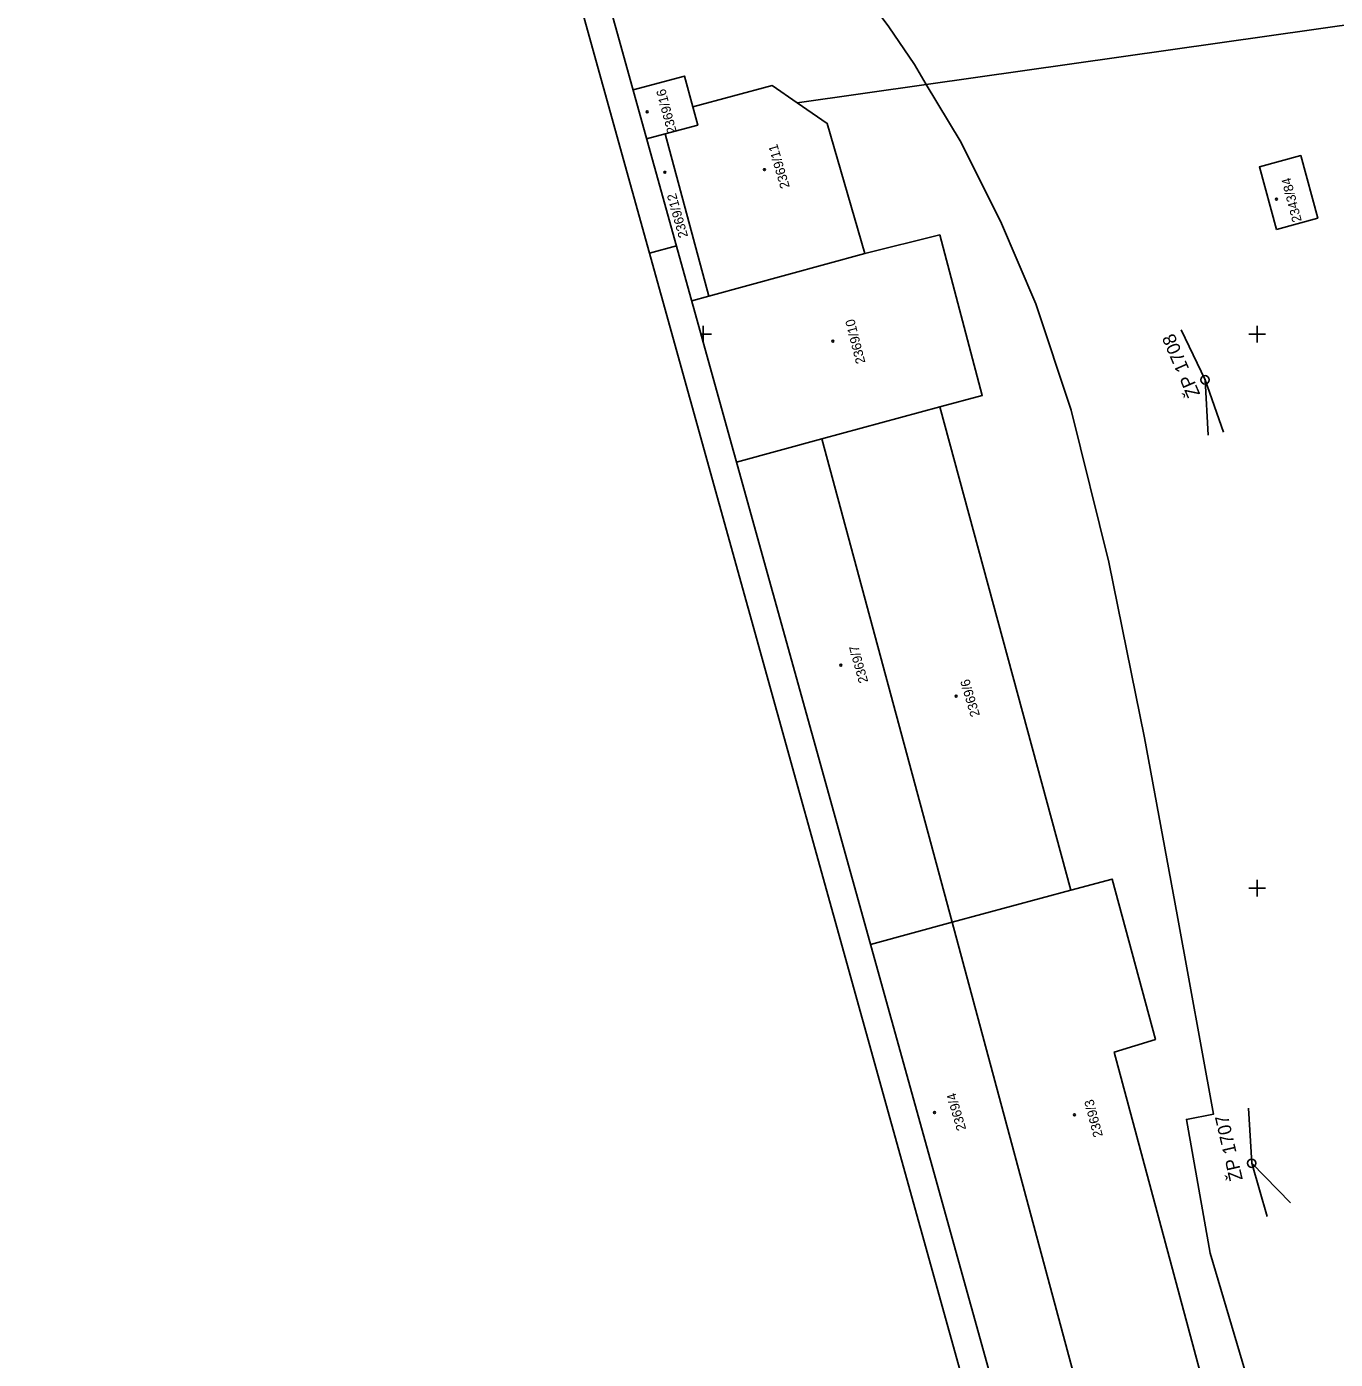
# Model space of a CAD drawing. Extents: x -821122 to -820555, y -1070892 to -1069801.
# Drawn here: x -821122.1 to -820885.9, y -1070485 to -1070244.5 of the extents above; entities that cross this region are included whole.
import ezdxf

# ---------------------------------------------------------------- set-up
doc = ezdxf.new("R2010")
doc.units = 0
for name, color, linetype in [('Hranice drážního pozemku', 7, 'Continuous'), ('Hranice parcel', 7, 'Continuous'), ('Parcelní čísla', 7, 'Continuous'), ('Ram', 7, 'Continuous'), ('Vrstva 61', 7, 'Continuous'), ('ZBP', 7, 'Continuous'), ('Značky budov', 7, 'Continuous')]:
    doc.layers.add(name, color=color, linetype=linetype)

msp = doc.modelspace()

# ---------------------------------------------------------------- linework, layer by layer
at = {"layer": 'Hranice drážního pozemku'}
for points in [[(-820959.73, -1070254.91), (-820961.88, -1070251.33), (-820966.49, -1070244.53), (-820975.99, -1070231.76), (-820986.52, -1070219.72), (-820997.71, -1070208.62), (-821016.02, -1070193.21), (-821033.38, -1070181.32)], [(-820768.36, -1070867.01), (-820772.76, -1070853.45), (-820780.56, -1070834.55), (-820786.59, -1070821.38), (-820797.89, -1070798.01), (-820802.49, -1070786.9), (-820807.86, -1070771.6), (-820839.34, -1070671.73), (-820847.49, -1070649.05), (-820862.12, -1070611.55), (-820870.18, -1070588.9), (-820893.88, -1070513.71), (-820901.78, -1070488.65), (-820908.48, -1070465.88), (-820912.77, -1070441.75), (-820907.91, -1070440.8), (-820914.43, -1070404.83), (-820920.34, -1070372.85), (-820926.76, -1070341.17), (-820933.59, -1070313.73), (-820939.94, -1070294.5), (-820946.33, -1070279.59), (-820953.63, -1070265.09), (-820959.73, -1070254.91)]]:
    msp.add_lwpolyline(points, dxfattribs=at)
at = {"layer": 'Hranice parcel'}
for p, q in [((-820959.73, -1070254.91), (-820835.88, -1070237.32)), ((-820959.73, -1070254.91), (-820983.06, -1070258.22)), ((-821006.88, -1070263.86), (-821010.2, -1070264.76)), ((-821006.88, -1070263.86), (-820998.99, -1070293.15)), ((-820970.82, -1070285.44), (-820998.99, -1070293.15)), ((-820998.99, -1070293.15), (-821002.07, -1070293.99)), ((-820957.29, -1070313.09), (-820978.59, -1070318.91)), ((-820957.29, -1070313.09), (-820933.62, -1070400.37)), ((-820978.59, -1070318.91), (-820993.99, -1070323.08)), ((-820978.59, -1070318.91), (-820955.07, -1070406.16)), ((-820933.62, -1070400.37), (-820955.07, -1070406.16)), ((-820955.07, -1070406.16), (-820969.8, -1070410.14)), ((-820955.07, -1070406.16), (-820931.21, -1070494.68))]:
    msp.add_line(p, q, dxfattribs=at)
for points in [[(-821033.38, -1070181.32), (-821016.02, -1070193.21), (-820997.71, -1070208.62), (-820986.52, -1070219.72), (-820975.99, -1070231.76), (-820966.49, -1070244.53), (-820961.88, -1070251.33), (-820959.73, -1070254.91)], [(-821001.88, -1070258.94), (-821003.37, -1070253.41), (-821012.65, -1070255.91)], [(-820983.06, -1070258.22), (-820987.52, -1070255.14), (-821001.88, -1070258.94)], [(-820768.36, -1070867.01), (-820772.76, -1070853.45), (-820780.56, -1070834.55), (-820786.59, -1070821.38), (-820797.89, -1070798.01), (-820802.49, -1070786.9), (-820807.86, -1070771.6), (-820839.34, -1070671.73), (-820847.49, -1070649.05), (-820862.12, -1070611.55), (-820870.18, -1070588.9), (-820893.88, -1070513.71), (-820901.78, -1070488.65), (-820908.48, -1070465.88), (-820912.77, -1070441.75), (-820907.91, -1070440.8), (-820914.43, -1070404.83), (-820920.34, -1070372.85), (-820926.76, -1070341.17), (-820933.59, -1070313.73), (-820939.94, -1070294.5), (-820946.33, -1070279.59), (-820953.63, -1070265.09), (-820959.73, -1070254.91)], [(-820983.06, -1070258.22), (-820977.6, -1070261.97), (-820970.82, -1070285.44)], [(-821001.88, -1070258.94), (-821000.98, -1070262.27), (-821006.88, -1070263.86)], [(-820896.54, -1070281.12), (-820899.6, -1070269.81), (-820892.15, -1070267.75), (-820889.06, -1070279.08), (-820896.54, -1070281.12)], [(-820970.82, -1070285.44), (-820957.3, -1070282.09), (-820949.63, -1070311.06), (-820957.29, -1070313.09)], [(-820933.62, -1070400.37), (-820926.16, -1070398.36), (-820918.36, -1070427.34), (-820925.8, -1070429.59), (-820909.9, -1070488.92), (-820931.21, -1070494.68)]]:
    msp.add_lwpolyline(points, dxfattribs=at)
at = {"layer": 'Ram'}
for p, q in [((-821004.84, -1070284.04), (-821009.66, -1070285.38)), ((-821009.66, -1070285.38), (-821004.84, -1070284.04))]:
    msp.add_line(p, q, dxfattribs=at)
for points in [[(-820837.51, -1070886.22), (-821115.94, -1069884.19), (-820839.42, -1069807.35)], [(-820840.99, -1070892.38), (-821122.1, -1069880.71)]]:
    msp.add_lwpolyline(points, dxfattribs=at)
at = {"layer": 'Vrstva 61'}
for p, q in [((-821000, -1070298.5), (-821000, -1070301.45)), ((-820900, -1070298.5), (-820900, -1070301.5)), ((-821000.4, -1070300), (-820998.5, -1070300)), ((-820901.5, -1070300), (-820898.5, -1070300)), ((-820901.5, -1070400), (-820898.5, -1070400)), ((-820900, -1070398.5), (-820900, -1070401.5))]:
    msp.add_line(p, q, dxfattribs=at)
at = {"layer": 'ZBP'}
for p, q in [((-820909.42, -1070308.24), (-820913.7, -1070299.2)), ((-820909.41, -1070308.28), (-820909.43, -1070308.19)), ((-820909.42, -1070308.24), (-820908.83, -1070318.22)), ((-820909.42, -1070308.24), (-820906.1, -1070317.67)), ((-820901, -1070449.66), (-820901.59, -1070439.68)), ((-820900.98, -1070449.71), (-820901.01, -1070449.61)), ((-820901, -1070449.66), (-820898.19, -1070459.26)), ((-820901, -1070449.66), (-820893.97, -1070456.77))]:
    msp.add_line(p, q, dxfattribs=at)
for centre in [(-820909.42, -1070308.24), (-820901, -1070449.66)]:
    msp.add_circle(centre, 0.756, dxfattribs=at)
at = {"layer": 'Značky budov'}
for centre in [(-821010.11, -1070259.85), (-820988.95, -1070270.3), (-821006.9, -1070270.78), (-820896.53, -1070275.64), (-820976.59, -1070301.24), (-820975.15, -1070359.75), (-820954.34, -1070365.35), (-820958.24, -1070440.5), (-820932.99, -1070440.92)]:
    msp.add_circle(centre, 0.175, dxfattribs=at)

# ---------------------------------------------------------------- texts
at = {"layer": 'Parcelní čísla'}
for s, rotation, p in [('2369/16', 104.9208, (-821004.74, -1070263.53)), ('2369/11', 106.2487, (-820984.35, -1070273.43)), ('2343/84', 104.6003, (-820891.94, -1070279.56)), ('2369/12', 105.7231, (-821002.71, -1070282.34)), ('2369/10', 104.2543, (-820970.71, -1070305.11)), ('2369/7', 105.4112, (-820970.2, -1070362.73)), ('2369/6', 106.4652, (-820950.03, -1070368.79)), ('2369/4', 106.2734, (-820952.51, -1070443.5)), ('2369/3', 104.6573, (-820927.84, -1070444.72))]:
    msp.add_text(s, height=1.7, rotation=rotation, dxfattribs=at).set_placement(p)
at = {"layer": 'ZBP'}
for s, rotation, p in [('ŽP 1708', 113.3783, (-820910.25, -1070310.83)), ('ŽP 1707', 103, (-820902.59, -1070452.57))]:
    msp.add_text(s, height=2.4, rotation=rotation, dxfattribs=at).set_placement(p)

doc.saveas('drawing.dxf')
